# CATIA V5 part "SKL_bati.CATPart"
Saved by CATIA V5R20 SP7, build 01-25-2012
Part number: SKL_bati
Publications: "Esquisse.1", "Droite.1", "Esquisse.2", "Droite.2"
Bounding box of the stored display mesh (mm): x 0 to 0, y 0 to 120, z 0 to 170
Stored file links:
  F:\IAO_placube\SKL_bati.CATPart
  F:\IAO_placube\Product1.CATProduct
  F:\IAO_placube\SKL_general.CATPart
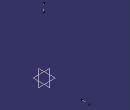
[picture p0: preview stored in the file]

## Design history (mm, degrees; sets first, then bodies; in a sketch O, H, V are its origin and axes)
Set1
  Plane1 "plan_ref": linked copy from another document
  Point1: linked copy from another document
  Point2: linked copy from another document
Body1 (main body)
  Sketch1 on Plane1, origin (0, 0, 0), H (0, 1, 0), V (0, 0, 1)
    line L1 (50, 0) -> (150, 0)
    point P1 (50, 0)
    reference projected point E1 (100, 0) from Point1
    coincidence: P1 H, E1 L1
    horizontal: L1 H
  Line1: type PtDir, RefPoint Point1, Direction Sketch1, Start 0, End 20
  Sketch2 on Plane1, origin (0, 0, 0), H (0, 1, 0), V (0, 0, 1)
    line L1 (0, 130) -> (0, 160)
    reference projected point E1 (0, 150) from Point2
    vertical: L1 V
    coincidence: E1 L1
  Line2: type PtDir, RefPoint Point2, Direction Sketch2, Start 0, End 20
